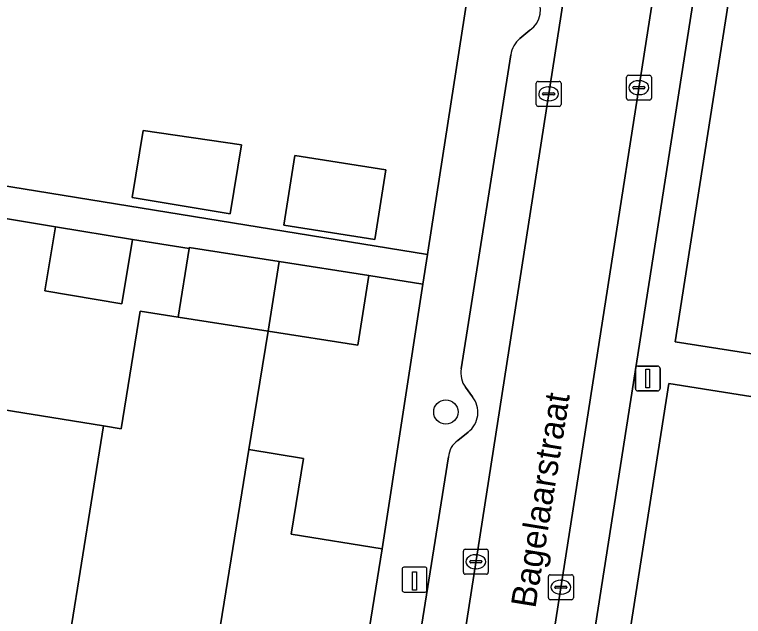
# Model space of a CAD drawing. Extents: x 163008 to 163854, y 382777 to 383982.
# Drawn here: x 163253.69 to 163282.98, y 383137.42 to 383161.59 of the extents above; entities that cross this region are included whole.
import ezdxf

# ---------------------------------------------------------------- set-up
doc = ezdxf.new("R2010")
doc.units = 0
for name, color, linetype in [('IMGEO_Boom', 7, 'Continuous'), ('IMGEO_Erf', 7, 'Continuous'), ('IMGEO_Groenvoorziening', 7, 'Continuous'), ('IMGEO_Kolk', 7, 'Continuous'), ('IMGEO_Laadpaal', 7, 'Continuous'), ('IMGEO_Lichtmast', 7, 'Continuous'), ('IMGEO_Muur', 7, 'Continuous'), ('IMGEO_Openbare_ruimte_label', 7, 'Continuous'), ('IMGEO_Pand', 7, 'Continuous'), ('IMGEO_Parkeervlak_open', 7, 'Continuous'), ('IMGEO_Rijbaan_lokaal_open', 7, 'Continuous'), ('IMGEO_Voetpad_open', 7, 'Continuous')]:
    doc.layers.add(name, color=color, linetype=linetype)

msp = doc.modelspace()

# ---------------------------------------------------------------- linework, layer by layer
at = {"layer": 'IMGEO_Boom'}
msp.add_circle((163271.018, 383145.631), 0.489, dxfattribs=at)
at = {"layer": 'IMGEO_Erf'}
msp.add_lwpolyline([(163243.502, 383173.822), (163241.409, 383159.573), (163241.456, 383159.566), (163245.155, 383159.023), (163244.781, 383156.485), (163241.083, 383157.028), (163241.035, 383157.035), (163240.986, 383156.699), (163270.282, 383151.95), (163270.324, 383152.219), (163271.991, 383163.012)], dxfattribs=at)
for points in [[(163258.412, 383154.236), (163258.857, 383156.936), (163262.803, 383156.356), (163262.348, 383153.588)], [(163268.605, 383155.354), (163268.166, 383152.558), (163264.507, 383153.133), (163264.946, 383155.929)], [(163260.699, 383152.192), (163258.423, 383152.549), (163257.994, 383149.974), (163254.904, 383150.489), (163255.333, 383153.064), (163252.672, 383153.508), (163252.243, 383150.933), (163252.191, 383150.622), (163248.23, 383151.204), (163248.655, 383154.098), (163248.664, 383154.154), (163241.153, 383155.367), (163241.123, 383155.183), (163239.36, 383144.836), (163245.271, 383143.881), (163251.032, 383142.951), (163251.522, 383145.997), (163257.264, 383145.068), (163257.974, 383144.953), (163258.74, 383149.682), (163260.267, 383149.442)], [(163270.099, 383150.762), (163267.917, 383151.105), (163267.478, 383148.309), (163263.872, 383148.876), (163263.102, 383144.124), (163265.297, 383143.769), (163264.805, 383140.728), (163268.457, 383140.137)]]:
    msp.add_lwpolyline(points, close=True, dxfattribs=at)
at = {"layer": 'IMGEO_Groenvoorziening'}
for points in [[(163284.671, 383176.706), (163280.237, 383148.453), (163286.065, 383147.534), (163290.5, 383175.79)], [(163285.801, 383145.855), (163279.973, 383146.774), (163275.529, 383118.456)]]:
    msp.add_lwpolyline(points, dxfattribs=at)
at = {"layer": 'IMGEO_Kolk'}
for p, q in [((163278.277, 383158.225), (163278.277, 383159.077)), ((163278.352, 383159.151), (163279.204, 383159.151)), ((163279.278, 383159.077), (163279.278, 383158.225)), ((163274.648, 383157.975), (163274.648, 383158.827)), ((163274.723, 383158.901), (163275.575, 383158.901)), ((163275.649, 383158.827), (163275.649, 383157.975)), ((163278.579, 383158.694), (163278.977, 383158.694)), ((163278.765, 383158.931), (163278.79, 383158.931)), ((163274.907, 383158.395), (163274.907, 383158.407)), ((163274.95, 383158.444), (163275.348, 383158.444)), ((163275.136, 383158.681), (163275.161, 383158.681)), ((163275.391, 383158.407), (163275.391, 383158.395)), ((163278.536, 383158.645), (163278.536, 383158.657)), ((163278.974, 383158.608), (163278.576, 383158.608)), ((163279.02, 383158.657), (163279.02, 383158.645)), ((163275.345, 383158.358), (163274.947, 383158.358)), ((163275.159, 383158.121), (163275.134, 383158.121)), ((163279.204, 383158.151), (163278.352, 383158.151)), ((163278.788, 383158.371), (163278.763, 383158.371)), ((163275.575, 383157.901), (163274.723, 383157.901)), ((163271.722, 383139.193), (163271.722, 383140.045)), ((163271.797, 383140.119), (163272.649, 383140.119)), ((163272.723, 383140.045), (163272.723, 383139.193)), ((163272.024, 383139.662), (163272.422, 383139.662)), ((163272.21, 383139.899), (163272.235, 383139.899)), ((163271.981, 383139.613), (163271.981, 383139.625)), ((163272.419, 383139.576), (163272.021, 383139.576)), ((163272.465, 383139.625), (163272.465, 383139.613)), ((163272.649, 383139.119), (163271.797, 383139.119)), ((163272.233, 383139.339), (163272.208, 383139.339)), ((163275.215, 383139.095), (163276.067, 383139.095)), ((163275.14, 383138.169), (163275.14, 383139.021)), ((163275.628, 383138.875), (163275.653, 383138.875)), ((163276.141, 383139.021), (163276.141, 383138.169)), ((163275.399, 383138.589), (163275.399, 383138.601)), ((163275.837, 383138.552), (163275.439, 383138.552)), ((163275.442, 383138.638), (163275.84, 383138.638)), ((163275.883, 383138.601), (163275.883, 383138.589)), ((163275.651, 383138.315), (163275.626, 383138.315)), ((163276.067, 383138.095), (163275.215, 383138.095))]:
    msp.add_line(p, q, dxfattribs=at)
for points in [[(163278.277, 383158.225), (163278.277, 383159.077)], [(163278.352, 383159.151), (163279.204, 383159.151)], [(163279.278, 383159.077), (163279.278, 383158.225)], [(163274.648, 383157.975), (163274.648, 383158.827)], [(163274.723, 383158.901), (163275.575, 383158.901)], [(163275.649, 383158.827), (163275.649, 383157.975)], [(163279.204, 383158.151), (163278.352, 383158.151)], [(163275.575, 383157.901), (163274.723, 383157.901)], [(163271.722, 383139.193), (163271.722, 383140.045)], [(163271.797, 383140.119), (163272.649, 383140.119)], [(163272.723, 383140.045), (163272.723, 383139.193)], [(163272.649, 383139.119), (163271.797, 383139.119)], [(163275.215, 383139.095), (163276.067, 383139.095)], [(163275.14, 383138.169), (163275.14, 383139.021)], [(163276.141, 383139.021), (163276.141, 383138.169)], [(163276.067, 383138.095), (163275.215, 383138.095)]]:
    msp.add_lwpolyline(points, dxfattribs=at)
for centre, radius, start, end in [((163278.354, 383159.075), 0.0765, 91.552, 178.448), ((163278.354, 383159.075), 0.0765, 91.552, 178.448), ((163279.202, 383159.075), 0.0765, 1.552, 88.448), ((163279.202, 383159.075), 0.0765, 1.552, 88.448), ((163274.725, 383158.825), 0.0765, 91.552, 178.448), ((163274.725, 383158.825), 0.0765, 91.552, 178.448), ((163275.573, 383158.825), 0.0765, 1.552, 88.448), ((163275.573, 383158.825), 0.0765, 1.552, 88.448), ((163278.576, 383158.654), 0.0403, 85.8775, 175.7526), ((163278.981, 383158.656), 0.0386, 1.7309, 96.639), ((163274.947, 383158.404), 0.0403, 85.8775, 175.7526), ((163274.944, 383158.394), 0.0366, 178.938, 274.7102), ((163275.348, 383158.401), 0.043, 264.8664, 352.4533), ((163275.352, 383158.406), 0.0386, 1.7309, 96.639), ((163278.573, 383158.644), 0.0366, 178.938, 274.7102), ((163278.977, 383158.651), 0.043, 264.8664, 352.4533), ((163278.354, 383158.227), 0.0765, 181.552, 268.448), ((163278.354, 383158.227), 0.0765, 181.552, 268.448), ((163279.202, 383158.227), 0.0765, 271.552, 358.448), ((163279.202, 383158.227), 0.0765, 271.552, 358.448), ((163274.725, 383157.977), 0.0765, 181.552, 268.448), ((163274.725, 383157.977), 0.0765, 181.552, 268.448), ((163275.573, 383157.977), 0.0765, 271.552, 358.448), ((163275.573, 383157.977), 0.0765, 271.552, 358.448), ((163271.799, 383140.043), 0.0765, 91.552, 178.448), ((163271.799, 383140.043), 0.0765, 91.552, 178.448), ((163272.647, 383140.043), 0.0765, 1.552, 88.448), ((163272.647, 383140.043), 0.0765, 1.552, 88.448), ((163272.021, 383139.622), 0.0403, 85.8775, 175.7526), ((163272.426, 383139.624), 0.0386, 1.7309, 96.639), ((163272.018, 383139.612), 0.0366, 178.938, 274.7102), ((163272.422, 383139.619), 0.043, 264.8664, 352.4533), ((163271.799, 383139.195), 0.0765, 181.552, 268.448), ((163271.799, 383139.195), 0.0765, 181.552, 268.448), ((163272.647, 383139.195), 0.0765, 271.552, 358.448), ((163272.647, 383139.195), 0.0765, 271.552, 358.448), ((163275.217, 383139.019), 0.0765, 91.552, 178.448), ((163275.217, 383139.019), 0.0765, 91.552, 178.448), ((163276.065, 383139.019), 0.0765, 1.552, 88.448), ((163276.065, 383139.019), 0.0765, 1.552, 88.448), ((163275.439, 383138.598), 0.0403, 85.8775, 175.7526), ((163275.436, 383138.588), 0.0366, 178.938, 274.7102), ((163275.84, 383138.595), 0.043, 264.8664, 352.4533), ((163275.844, 383138.6), 0.0386, 1.7309, 96.639), ((163275.217, 383138.171), 0.0765, 181.552, 268.448), ((163275.217, 383138.171), 0.0765, 181.552, 268.448), ((163276.065, 383138.171), 0.0765, 271.552, 358.448), ((163276.065, 383138.171), 0.0765, 271.552, 358.448)]:
    msp.add_arc(centre, radius, start, end, dxfattribs=at)
for centre, major_axis, ratio, start_param, end_param in [((163278.764, 383158.651), (-0.387, 0.002), 0.722429, 4.712389, 7.853982), ((163278.789, 383158.651), (-0.39, 0.002), 0.717154, 1.570796, 4.712389), ((163275.135, 383158.401), (-0.387, 0.002), 0.722429, 4.712389, 7.853982), ((163275.16, 383158.401), (-0.39, 0.002), 0.717154, 1.570796, 4.712389), ((163272.209, 383139.619), (-0.387, 0.002), 0.722429, 4.712389, 7.853982), ((163272.234, 383139.619), (-0.39, 0.002), 0.717154, 1.570796, 4.712389), ((163275.627, 383138.595), (-0.387, 0.002), 0.722429, 4.712389, 7.853982), ((163275.652, 383138.595), (-0.39, 0.002), 0.717154, 1.570796, 4.712389)]:
    msp.add_ellipse(centre, major_axis=major_axis, ratio=ratio, start_param=start_param, end_param=end_param, dxfattribs=at)
at = {"layer": 'IMGEO_Laadpaal'}
for p, q in [((163270.175, 383139.401), (163269.334, 383139.401)), ((163270.175, 383139.401), (163269.334, 383139.401)), ((163269.259, 383139.317), (163269.259, 383138.476)), ((163269.259, 383139.317), (163269.259, 383138.476)), ((163270.259, 383138.485), (163270.259, 383139.326)), ((163270.259, 383138.485), (163270.259, 383139.326)), ((163269.343, 383138.401), (163270.184, 383138.401)), ((163269.343, 383138.401), (163270.184, 383138.401))]:
    msp.add_line(p, q, dxfattribs=at)
msp.add_lwpolyline([(163269.674, 383139.214), (163269.834, 383139.214), (163269.834, 383138.481), (163269.674, 383138.481), (163269.674, 383139.214)], dxfattribs=at)
for centre, start, end in [((163269.337, 383139.323), 92.4484, 184.2845), ((163269.337, 383139.323), 92.4484, 184.2845), ((163270.181, 383139.323), 2.4484, 94.2845), ((163270.181, 383139.323), 2.4484, 94.2845), ((163270.181, 383138.479), 272.4484, 4.2845), ((163270.181, 383138.479), 272.4484, 4.2845), ((163269.337, 383138.479), 182.4484, 274.2845), ((163269.337, 383138.479), 182.4484, 274.2845)]:
    msp.add_arc(centre, 0.0779, start, end, dxfattribs=at)
at = {"layer": 'IMGEO_Lichtmast'}
for p, q in [((163278.634, 383146.575), (163278.634, 383147.375)), ((163278.634, 383147.375), (163278.634, 383146.575)), ((163278.734, 383147.475), (163279.524, 383147.475)), ((163279.524, 383147.475), (163278.734, 383147.475)), ((163279.624, 383147.375), (163279.624, 383146.575)), ((163279.624, 383146.575), (163279.624, 383147.375)), ((163279.524, 383146.475), (163278.734, 383146.475)), ((163278.734, 383146.475), (163279.524, 383146.475))]:
    msp.add_line(p, q, dxfattribs=at)
msp.add_lwpolyline([(163279.054, 383147.35), (163279.204, 383147.35), (163279.204, 383146.6), (163279.054, 383146.6), (163279.054, 383147.35)], dxfattribs=at)
for centre, start, end in [((163278.734, 383147.375), 90, 180), ((163278.734, 383147.375), 90, 180), ((163279.524, 383147.375), 0, 90), ((163279.524, 383147.375), 360, 90), ((163278.734, 383146.575), 180, 270), ((163278.734, 383146.575), 180, 270), ((163279.524, 383146.575), 270, 0), ((163279.524, 383146.575), 270, 0)]:
    msp.add_arc(centre, 0.1, start, end, dxfattribs=at)
at = {"layer": 'IMGEO_Muur'}
for points in [[(163271.991, 383163.012), (163270.324, 383152.219)], [(163268.457, 383140.137), (163270.099, 383150.762)]]:
    msp.add_lwpolyline(points, dxfattribs=at)
at = {"layer": 'IMGEO_Pand'}
for points in [[(163258.412, 383154.236), (163262.348, 383153.588), (163262.803, 383156.356), (163258.857, 383156.936)], [(163268.166, 383152.558), (163268.605, 383155.354), (163264.946, 383155.929), (163264.507, 383153.133)], [(163258.423, 383152.549), (163255.333, 383153.064), (163254.904, 383150.489), (163257.994, 383149.974)], [(163264.325, 383151.669), (163260.706, 383152.238), (163260.699, 383152.192), (163260.267, 383149.442), (163263.872, 383148.876)], [(163264.325, 383151.669), (163263.872, 383148.876), (163267.478, 383148.309), (163267.917, 383151.105)], [(163263.102, 383144.124), (163263.872, 383148.876), (163260.267, 383149.442), (163258.74, 383149.682), (163257.974, 383144.953), (163257.264, 383145.068), (163255.5, 383134.044), (163261.316, 383133.105)], [(163255.5, 383134.044), (163257.264, 383145.068), (163251.522, 383145.997), (163251.032, 383142.951), (163249.739, 383134.974)], [(163263.102, 383144.124), (163261.316, 383133.105), (163267.168, 383132.16), (163268.457, 383140.137), (163264.805, 383140.728), (163265.297, 383143.769)]]:
    msp.add_lwpolyline(points, close=True, dxfattribs=at)
at = {"layer": 'IMGEO_Parkeervlak_open'}
for points in [[(163271.119, 383143.834), (163269.499, 383133.678), (163271.253, 383133.395), (163280.323, 383191.611), (163278.747, 383191.863), (163278.555, 383191.425), (163275.791, 383174.012)], [(163281.778, 383177.835), (163274.739, 383132.832), (163274.214, 383129.473), (163274.189, 383129.31), (163272.691, 383119.736)], [(163274.685, 383122.106), (163282.934, 383174.782)], [(163274.398, 383160.956), (163273.997, 383160.619)], [(163273.631, 383159.967), (163271.638, 383147.366)], [(163271.805, 383146.621), (163272.091, 383146.241)], [(163271.91, 383144.818), (163271.501, 383144.48)]]:
    msp.add_lwpolyline(points, dxfattribs=at)
for centre, radius, start, end in [((163273.801, 383161.779), 1.017, 305.9492, 34.5024), ((163274.562, 383159.873), 0.936, 127.1524, 174.2323), ((163272.589, 383147.188), 0.968, 169.4016, 215.8676), ((163271.298, 383145.619), 1.008, 307.3744, 38.1279), ((163272.001, 383143.748), 0.886, 124.3554, 174.4503)]:
    msp.add_arc(centre, radius, start, end, dxfattribs=at)
at = {"layer": 'IMGEO_Rijbaan_lokaal_open'}
msp.add_lwpolyline([(163280.323, 383191.611), (163271.253, 383133.395), (163274.739, 383132.832), (163281.778, 383177.835), (163281.931, 383179.059), (163282.521, 383182.549), (163283.842, 383191.049)], close=True, dxfattribs=at)
at = {"layer": 'IMGEO_Voetpad_open'}
for points in [[(163265.57, 383054.888), (163269.985, 383082.335), (163275.662, 383081.422), (163275.873, 383083.085), (163270.193, 383083.981), (163274.68, 383112.429), (163274.673, 383112.705), (163275.529, 383118.456), (163279.973, 383146.774), (163285.801, 383145.855), (163286.065, 383147.534), (163280.237, 383148.453), (163284.671, 383176.706)], [(163282.934, 383174.782), (163274.685, 383122.106)], [(163271.991, 383163.012), (163270.324, 383152.219), (163270.282, 383151.95), (163270.099, 383150.762), (163268.457, 383140.137), (163267.168, 383132.16), (163266.909, 383130.633), (163266.291, 383126.455), (163266.288, 383126.43), (163264.176, 383112.34), (163264.173, 383112.32), (163263.52, 383108.014), (163263.279, 383106.473), (163261.93, 383097.996), (163261.735, 383098.027), (163259.619, 383084.866), (163259.384, 383083.403), (163257.275, 383070.289), (163255.991, 383062.434), (163254.811, 383055.03)], [(163273.997, 383160.619), (163274.398, 383160.956)], [(163271.638, 383147.366), (163273.631, 383159.967)], [(163252.672, 383153.508), (163255.333, 383153.064), (163258.423, 383152.549), (163260.699, 383152.192), (163260.706, 383152.238), (163264.325, 383151.669), (163267.917, 383151.105), (163270.099, 383150.762), (163270.282, 383151.95), (163240.986, 383156.699)], [(163272.091, 383146.241), (163271.805, 383146.621)], [(163271.501, 383144.48), (163271.91, 383144.818)], [(163269.474, 383133.523), (163269.499, 383133.678), (163271.119, 383143.834)]]:
    msp.add_lwpolyline(points, dxfattribs=at)
for centre, radius, start, end in [((163273.801, 383161.779), 1.017, 305.9492, 34.5024), ((163274.562, 383159.873), 0.936, 127.1524, 174.2323), ((163272.589, 383147.188), 0.968, 169.4016, 215.8676), ((163271.298, 383145.619), 1.008, 307.3744, 38.1279), ((163272.001, 383143.748), 0.886, 124.3554, 174.4503)]:
    msp.add_arc(centre, radius, start, end, dxfattribs=at)

# ---------------------------------------------------------------- texts
at = {"layer": 'IMGEO_Openbare_ruimte_label'}
msp.add_text('Bagelaarstraat', height=1, rotation=80.792, dxfattribs=at).set_placement((163274.612, 383137.722))

doc.saveas('drawing.dxf')
